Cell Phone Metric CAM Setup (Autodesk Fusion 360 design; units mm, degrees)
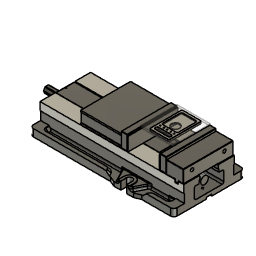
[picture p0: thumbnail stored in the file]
description: HaasClamp
derived_base_feature "Derived Base Feature" bodies "Main Body"
align "Align1"
sketch "Sketch1" plane through (0, 0, 0) normal (0, 0, -1) x axis (1, 0, 0)
  line L1 (30, 46.5) -> (30, -46.5)
  line L2 (-26.5, 50) -> (26.5, 50)
  line L3 (-30, -46.5) -> (-30, 46.5)
  line L4 (26.5, -50) -> (-26.5, -50)
  line L5 (-23.5, 38.5) -> (-23.5, 36)
  line L6 (20, 42) -> (-20, 42)
  line L7 (23.5, 36) -> (23.5, 38.5)
  line L8 (-20, 32.5) -> (20, 32.5)
  line L9 (-50.8, -55) -> (50.8, -55)
  line L10 (-50.8, 55) -> (-50.8, -55)
  line L11 (50.8, 55) -> (-50.8, 55)
  line L12 (50.8, -55) -> (50.8, 55)
  line L13 (-50.8, 55) -> (50.8, -55)
  line L14 (50.8, 55) -> (-50.8, -55)
  arc A1 centre (26.5, -46.5) radius 3.5 clockwise from (30, -46.5) to (26.5, -50)
  arc A2 centre (26.5, 46.5) radius 3.5 clockwise from (26.5, 50) to (30, 46.5)
  arc A3 centre (-26.5, 46.5) radius 3.5 clockwise from (-30, 46.5) to (-26.5, 50)
  arc A4 centre (-26.5, -46.5) radius 3.5 clockwise from (-26.5, -50) to (-30, -46.5)
  circle C1 centre (10.5, 25) radius 2.117
  circle C2 centre (-10.5, 25) radius 2.117
  circle C3 centre (-21, 25) radius 2.117
  circle C4 centre (0, 25) radius 2.117
  circle C5 centre (21, 25) radius 2.117
  arc A5 centre (-20, 38.5) radius 3.5 clockwise from (-23.5, 38.5) to (-20, 42)
  arc A6 centre (20, 38.5) radius 3.5 clockwise from (20, 42) to (23.5, 38.5)
  arc A7 centre (20, 36) radius 3.5 clockwise from (23.5, 36) to (20, 32.5)
  arc A8 centre (-20, 36) radius 3.5 clockwise from (-20, 32.5) to (-23.5, 36)
  circle C6 centre (0, 0) radius 12.5
  point P36 (0, 0)
  point P1 (0, 0)
  point P34 (-50.8, 55)
  point P35 (50.8, 55)
  point P32 (50.8, -55)
  horizontal L9
  perpendicular L9 L10
  parallel L9 L11
  parallel L10 L12
  coincident L13 P36
  coincident L14 P36
  coincident P1 P36
  dimension "d1" distance P34 P35 = 101.6
  dimension "d2" distance P32 P35 = 110
extrude "Extrude1" new body sketch "Sketch1" profile of L9 L10 L11 L12 against normal blind 6 bodies "Stock"
base_feature "Base Feature1"
base_feature "Base Feature1"
base_feature "Base Feature1"
base_feature "Base Feature1"
base_feature "Base Feature1"
base_feature "Base Feature1"
base_feature "Base Feature1"
base_feature "Base Feature1"
base_feature "Base Feature1"
base_feature "Base Feature1"
as_built_joint "As-built1"
as_built_joint "As-built2"
as_built_joint "As-built3"
joint_origin "JointOrigin1" OffsetX 0 OffsetY 0 OffsetZ 0 AngleZ 0
joint "Assemble1" alignAngle 180 alignOffsetX 0 alignOffsetY 0 alignOffsetZ 0 (= "jaw_width_haas_050002") SlideMaximum 22.5 SlideMinimum 0
position "Position1"
sketch "Sketch1" plane through (0, -72.5, 0) normal (0, -1, 0) x axis (1, 0, 0)
  line L1 (75, 73) -> (-75, 73)
  line L2 (76, 74) -> (75, 73)
  line L3 (76, 116.5) -> (76, 74)
  line L4 (75, 117.5) -> (76, 116.5)
  line L5 (-75, 117.5) -> (75, 117.5)
  line L6 (-76, 116.5) -> (-75, 117.5)
  line L7 (-76, 74) -> (-76, 116.5)
  line L8 (-75, 73) -> (-76, 74)
  line L9 (76.4, 114.275) -> (-76, 114.275)
  line L10 (76.4, 73) -> (76.4, 114.275)
  line L11 (-76, 73) -> (76.4, 73)
  line L12 (-76, 114.275) -> (-76, 73)
  circle C1 centre (49.21, 96.8) radius 11
  circle C2 centre (-49.21, 96.8) radius 11
  point P14 (76.4, 73)
  point P12 (-76, 114.275)
  point P13 (76.4, 114.275)
  horizontal L9
  vertical L10
  horizontal L11
  vertical L12
  coincident L1 P14
  coincident L7 P12
  dimension "d16" distance P12 P13 = 152.4
  dimension "d17" distance P13 P14 = 41.275
place_component sketch "Sketch1"
extrude "Extrude1" new body sketch "Sketch1" profile of L1 L2 L3 L7 L8 C1 C2 L9 L11 L12 along normal blind 3.175
place_component sketch "Sketch1"
extrude "Extrude1" sketch "Sketch1" profile of L1 L2 L3 L7 L8 C1 C2 L9 L11 L12 blind -3.175
as_built_joint "As-built5"
as_built_joint "As-built6"
position "Position1"
ground "Pin"
position "Position2"
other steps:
create_component "CreateComponent1"
create_component "CreateComponent2"
create_component "CreateComponent3"
create_component "CreateComponent4"
create_component "CreateComponent5"
create_component "CreateComponent6"
create_component "CreateComponent7"
create_component "CreateComponent8"
create_component "CreateComponent9"
create_component "CreateComponent10"
joint_origin "JointOrigin10"
joint_origin "JointOrigin11"
create_component "CreateComponent11" sketch "Sketch1"
create_component "CreateComponent12" sketch "Sketch1"
create_component "CreateComponent1"
named bodies: "Main Body", "Stock"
